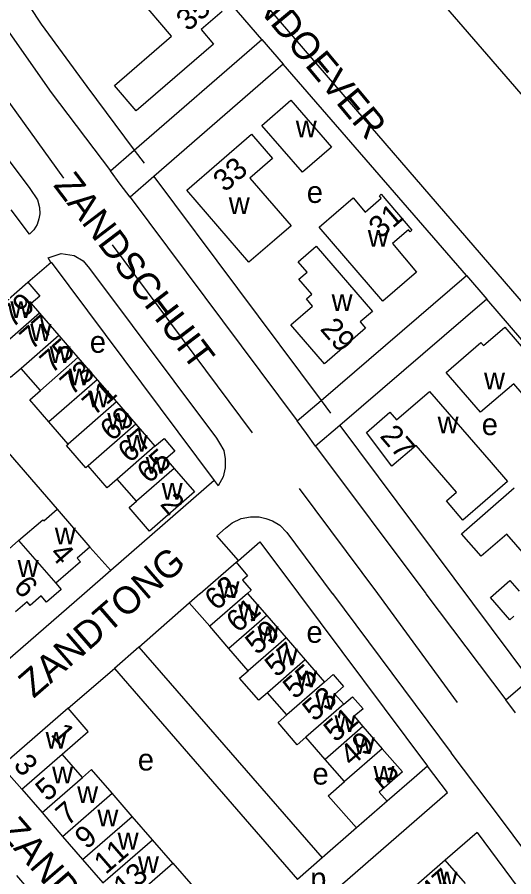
# Model space of a CAD drawing. Extents: x 155854 to 157362, y 383621 to 384685.
# Drawn here: x 156615.7 to 156707.1, y 384447.9 to 384605.9 of the extents above; entities that cross this region are included whole.
import ezdxf

# ---------------------------------------------------------------- set-up
doc = ezdxf.new("R2010")
doc.units = 0
for name, color, linetype in [('BLT_Basislijn', 7, 'Continuous'), ('BLT_Bebouwing', 7, 'Continuous'), ('BLT_Centroide', 7, 'Continuous'), ('BLT_Huisnummer', 7, 'Continuous'), ('BLT_Huisnummer_ tussenligend', 7, 'Continuous'), ('BLT_Huisnummer_reeks', 7, 'Continuous'), ('BLT_Onderverdeling_panden', 7, 'Continuous'), ('BLT_Straatnaam', 7, 'Continuous'), ('BLT_Vlakafsluiter', 7, 'Continuous')]:
    doc.layers.add(name, color=color, linetype=linetype)

msp = doc.modelspace()

# ---------------------------------------------------------------- linework, layer by layer
at = {"layer": 'BLT_Basislijn'}
for p, q in [((156738.35, 384519.08), (156620.78, 384655.36)), ((156660.68, 384601.84), (156664.6, 384597.3)), ((156632.85, 384577.67), (156637.24, 384581.48)), ((156637.24, 384581.48), (156639.05, 384579.08)), ((156640.85, 384576.67), (156636.46, 384572.86)), ((156636.46, 384572.86), (156634.65, 384575.26)), ((156633.18, 384564.07), (156658.93, 384529.55)), ((156617.64, 384557.2), (156621.94, 384560.91)), ((156698.32, 384558.42), (156702.06, 384554.11)), ((156676.7, 384539.93), (156676.7, 384539.94)), ((156667.23, 384531.71), (156671.59, 384535.45)), ((156671.59, 384535.45), (156673.31, 384533.17)), ((156609.87, 384530.7), (156623.06, 384515.49)), ((156675.02, 384530.89), (156670.57, 384527.07)), ((156670.57, 384527.07), (156668.9, 384529.39)), ((156651.95, 384520.75), (156632.95, 384504.22)), ((156651.95, 384520.75), (156652.68, 384519.76)), ((156629.09, 384508.54), (156632.95, 384504.22)), ((156656.38, 384506.09), (156660.35, 384509.5)), ((156660.35, 384509.5), (156667.45, 384500)), ((156655.99, 384505.77), (156656.38, 384506.09)), ((156632.95, 384504.22), (156628.09, 384500)), ((156628.07, 384499.98), (156591.85, 384468.53)), ((156628.09, 384500), (156628.07, 384499.98)), ((156667.45, 384500), (156667.46, 384499.98)), ((156667.46, 384499.98), (156691.17, 384468.24)), ((156638.1, 384490.13), (156647.36, 384498.28)), ((156638.1, 384490.13), (156633.62, 384486.24)), ((156638.1, 384490.13), (156671.77, 384451.38)), ((156625.08, 384478.9), (156633.62, 384486.24)), ((156633.62, 384486.24), (156667.24, 384447.45)), ((156705.61, 384480.46), (156709.91, 384484.17)), ((156678.11, 384456.92), (156671.77, 384451.38)), ((156700.29, 384456.04), (156694.41, 384450.96)), ((156700.29, 384456.04), (156731.11, 384414.78)), ((156671.77, 384451.38), (156667.24, 384447.45))]:
    msp.add_line(p, q, dxfattribs=at)
for points in [[(156640.63, 384670.01), (156709.96, 384590.03), (156761.05, 384531.07)], [(156660.68, 384601.84), (156620.18, 384648.79)], [(156602.64, 384633.55), (156611.21, 384618.58), (156613.55, 384614.63), (156620.14, 384604.65), (156628.52, 384593.18), (156637.24, 384581.48)], [(156598.66, 384627.58), (156608.28, 384611.57), (156621.98, 384592.1), (156632.85, 384577.67)], [(156593.76, 384619.32), (156609.39, 384596.86), (156624.21, 384576.36)], [(156584.74, 384610.72), (156588.67, 384613.62), (156618, 384574.45), (156619.46, 384572.38), (156619.82, 384570.92), (156619.84, 384569.78), (156619.71, 384568.89), (156619.36, 384567.83), (156618.76, 384566.86), (156617.99, 384566.04), (156614.62, 384570.53)], [(156637.24, 384581.48), (156660.68, 384601.84)], [(156664.6, 384597.3), (156640.85, 384576.67)], [(156698.32, 384558.42), (156664.6, 384597.3)], [(156640.85, 384576.67), (156671.59, 384535.45)], [(156636.46, 384572.86), (156667.23, 384531.71)], [(156621.88, 384560.86), (156621.41, 384561.72), (156623.76, 384562.5), (156626.21, 384562.11), (156627.82, 384561.16), (156629.03, 384559.75), (156652.39, 384528.52), (156652.94, 384527.66), (156653.7, 384526.26), (156653.93, 384524.73), (156653.93, 384523.09), (156653.61, 384521.44), (156652.68, 384519.76)], [(156621.94, 384560.91), (156651.95, 384520.75)], [(156671.59, 384535.45), (156698.32, 384558.42)], [(156702.06, 384554.11), (156675.02, 384530.89)], [(156739.97, 384510.11), (156702.06, 384554.11)], [(156675.02, 384530.89), (156709.91, 384484.17)], [(156670.57, 384527.07), (156690.84, 384500)], [(156682.02, 384500), (156667.6, 384519.3)], [(156656.38, 384506.09), (156652.44, 384510.61), (156654.01, 384512.01), (156655.27, 384512.99), (156656.87, 384513.78), (156658.62, 384514.06), (156660.19, 384514.06), (156661.43, 384513.81), (156662.65, 384513.34), (156664, 384512.55), (156665.28, 384511.21), (156673.66, 384500)], [(156673.66, 384500), (156673.67, 384499.98)], [(156673.67, 384499.98), (156695.52, 384470.73)], [(156682.04, 384499.98), (156682.02, 384500)], [(156696.72, 384479.99), (156682.04, 384499.98)], [(156690.84, 384500), (156690.85, 384499.98)], [(156690.89, 384499.93), (156705.61, 384480.46)], [(156726.96, 384411.19), (156730.91, 384406.67), (156732.14, 384407.62), (156733.47, 384408.89), (156734.43, 384410.44), (156734.94, 384411.69), (156735.4, 384413.39), (156735.49, 384414.94), (156735.24, 384416.83), (156734.81, 384418.13), (156704.77, 384458.46), (156695.52, 384470.73)], [(156648.22, 384422.86), (156694.85, 384463.4), (156691.17, 384468.24)], [(156691.17, 384468.24), (156688.74, 384466.13), (156683.73, 384461.82)]]:
    msp.add_lwpolyline(points, dxfattribs=at)
at = {"layer": 'BLT_Bebouwing'}
for p, q in [((156644.1, 384602.46), (156634.31, 384613.86)), ((156653.39, 384607), (156649.52, 384603.65)), ((156649.52, 384603.65), (156651.83, 384600.98)), ((156633.58, 384593.4), (156644.1, 384602.46)), ((156651.83, 384600.98), (156637.61, 384588.7)), ((156637.61, 384588.7), (156633.58, 384593.4)), ((156660.73, 384586.05), (156666.06, 384590.66)), ((156666.06, 384590.66), (156673.49, 384582.05)), ((156668.16, 384577.45), (156660.73, 384586.05)), ((156646.91, 384574.14), (156658.83, 384584.41)), ((156658.83, 384584.41), (156662.67, 384579.95)), ((156673.49, 384582.05), (156668.16, 384577.45)), ((156662.67, 384579.95), (156658.49, 384576.36)), ((156658.32, 384560.9), (156646.91, 384574.14)), ((156663.01, 384564.94), (156658.32, 384560.9)), ((156609.12, 384549.79), (156617.64, 384557.2)), ((156619.81, 384551.5), (156623.34, 384547.43)), ((156623.34, 384547.43), (156626.88, 384543.36)), ((156626.88, 384543.36), (156630.43, 384539.27)), ((156630.43, 384539.27), (156633.97, 384535.2)), ((156685.45, 384531.91), (156691.56, 384537.15)), ((156691.56, 384537.15), (156702.88, 384524.08)), ((156633.97, 384535.2), (156637.51, 384531.12)), ((156679.94, 384529.62), (156684.25, 384533.32)), ((156684.25, 384533.32), (156685.45, 384531.91)), ((156625.09, 384527.44), (156621.54, 384531.54)), ((156637.51, 384531.12), (156641.04, 384527.06)), ((156684.63, 384523.39), (156679.94, 384529.62)), ((156689.09, 384527.22), (156684.63, 384523.39)), ((156696.49, 384518.6), (156689.09, 384527.22)), ((156702.88, 384524.08), (156705.89, 384520.57)), ((156644.57, 384522.99), (156648.3, 384518.69)), ((156697.44, 384510.99), (156707.13, 384519.39)), ((156705.89, 384520.57), (156697.66, 384513.5)), ((156648.3, 384518.69), (156640.01, 384511.48)), ((156694.64, 384517.02), (156696.49, 384518.6)), ((156697.66, 384513.5), (156694.64, 384517.02)), ((156623.06, 384515.49), (156629.09, 384508.54)), ((156701.04, 384506.84), (156697.44, 384510.99)), ((156705.75, 384510.91), (156701.04, 384506.84)), ((156711.92, 384503.78), (156705.75, 384510.91)), ((156649.34, 384500), (156655.99, 384505.77)), ((156702.75, 384499.28), (156706.34, 384502.39)), ((156706.34, 384502.39), (156708.04, 384500.42)), ((156647.36, 384498.28), (156649.32, 384499.98)), ((156649.32, 384499.98), (156649.34, 384500)), ((156706.31, 384495.18), (156702.75, 384499.28)), ((156617.51, 384498.48), (156615.4, 384496.65)), ((156618.11, 384497.8), (156617.51, 384498.48)), ((156707.06, 384495.81), (156706.31, 384495.18)), ((156627.71, 384466.19), (156623.98, 384470.48)), ((156683.73, 384461.82), (156678.11, 384456.92)), ((156644.32, 384450.43), (156648.06, 384446.12)), ((156694.41, 384450.96), (156685.32, 384443.08)), ((156698.15, 384446.66), (156694.41, 384450.96)), ((156619.35, 384443.86), (156615.62, 384448.16))]:
    msp.add_line(p, q, dxfattribs=at)
for points in [[(156658.49, 384576.36), (156666.07, 384567.58), (156663.01, 384564.94)], [(156617.64, 384557.2), (156619.85, 384554.66), (156618.26, 384553.28), (156619.81, 384551.5)], [(156701.47, 384545.58), (156705.38, 384548.95), (156719.42, 384532.65), (156712.37, 384526.58), (156708.8, 384530.72), (156711.68, 384533.21), (156707.05, 384538.55)], [(156694.59, 384540.65), (156700.96, 384546.14), (156701.47, 384545.58)], [(156616.42, 384541.38), (156614.46, 384539.68), (156610.93, 384543.75), (156612.89, 384545.45)], [(156619.96, 384537.31), (156616.42, 384541.38)], [(156707.05, 384538.55), (156700.93, 384533.3), (156694.59, 384540.65)], [(156621.54, 384531.54), (156618, 384535.61), (156619.96, 384537.31)], [(156628.75, 384523.47), (156628.32, 384523.11), (156624.78, 384527.19), (156625.09, 384527.44)], [(156641.04, 384527.06), (156642.72, 384528.49), (156644.72, 384526.18), (156643.05, 384524.73), (156644.57, 384522.99)], [(156634.12, 384521.01), (156632.27, 384519.41), (156628.75, 384523.47)], [(156637.63, 384516.96), (156634.12, 384521.01)], [(156640.01, 384511.48), (156636.28, 384515.79), (156637.63, 384516.96)], [(156615.96, 384509.72), (156620.39, 384513.56), (156620.59, 384513.34), (156623.06, 384515.49)], [(156609.37, 384503.59), (156611.48, 384505.43), (156611.28, 384505.65), (156615.96, 384509.72)], [(156629.09, 384508.54), (156626.75, 384506.51), (156627.35, 384505.83), (156622.79, 384501.87)], [(156655.99, 384505.77), (156658.08, 384503.24), (156657.15, 384502.44), (156658.76, 384500.59), (156658.07, 384500)], [(156622.79, 384501.87), (156623.77, 384500.74), (156621.1, 384498.41), (156620.12, 384499.54), (156618.11, 384497.8)], [(156658.07, 384500), (156658.09, 384499.98)], [(156658.09, 384499.98), (156661.61, 384495.93)], [(156658.09, 384499.98), (156658.09, 384499.98)], [(156651.11, 384493.97), (156647.36, 384498.28)], [(156661.61, 384495.93), (156665.15, 384491.86)], [(156654.65, 384489.89), (156651.11, 384493.97)], [(156665.15, 384491.86), (156668.68, 384487.79)], [(156658.19, 384485.81), (156654.65, 384489.89)], [(156668.68, 384487.79), (156672.23, 384483.71)], [(156661.73, 384481.74), (156660.14, 384480.36), (156656.6, 384484.43), (156658.19, 384485.81)], [(156672.23, 384483.71), (156673.82, 384485.08), (156675.73, 384482.89), (156674.14, 384481.5), (156675.77, 384479.63)], [(156665.27, 384477.67), (156661.73, 384481.74)], [(156675.77, 384479.63), (156677.39, 384481.03), (156679.32, 384478.78), (156677.67, 384477.44), (156679.31, 384475.55)], [(156625.08, 384478.9), (156612.84, 384468.27)], [(156623.98, 384470.48), (156628.77, 384474.64), (156625.08, 384478.9)], [(156668.82, 384473.59), (156667.22, 384472.2), (156663.68, 384476.28), (156665.27, 384477.67)], [(156679.31, 384475.55), (156682.86, 384471.47)], [(156672.36, 384469.51), (156668.82, 384473.59)], [(156682.86, 384471.47), (156686.57, 384467.2)], [(156675.9, 384465.43), (156672.36, 384469.51)], [(156612.84, 384468.27), (156616.54, 384464.01)], [(156633.16, 384463.28), (156629.37, 384467.64), (156627.71, 384466.19)], [(156686.57, 384467.2), (156682.29, 384463.48), (156683.73, 384461.82)], [(156616.54, 384464.01), (156620.27, 384459.72)], [(156678.11, 384456.92), (156672.93, 384462.83), (156675.9, 384465.43)], [(156636.85, 384459.03), (156633.16, 384463.28)], [(156620.27, 384459.72), (156624.06, 384455.36)], [(156640.59, 384454.73), (156636.85, 384459.03)], [(156624.06, 384455.36), (156627.74, 384451.12)], [(156644.32, 384450.43), (156640.59, 384454.73)], [(156627.74, 384451.12), (156631.48, 384446.82)]]:
    msp.add_lwpolyline(points, dxfattribs=at)
for points in [[(156671.23, 384567.32), (156677.48, 384572.71), (156679.72, 384570.11), (156682.67, 384572.66), (156682.32, 384573.07), (156682.67, 384573.38), (156688.32, 384566.81), (156687.97, 384566.5), (156687.66, 384566.86), (156684.72, 384564.34), (156689.16, 384559.08), (156682.96, 384553.74)], [(156666.04, 384549.36), (156670.04, 384552.81), (156668.89, 384554.15), (156669.89, 384555.01), (156667.52, 384557.76), (156669.02, 384559.05), (156667.37, 384560.97), (156670.69, 384563.83), (156681.03, 384551.85), (156678.78, 384549.91), (156679.79, 384548.74), (156672.22, 384542.21)]]:
    msp.add_lwpolyline(points, close=True, dxfattribs=at)
at = {"layer": 'BLT_Onderverdeling_panden'}
for p, q in [((156619.81, 384551.5), (156612.89, 384545.45)), ((156623.34, 384547.43), (156616.42, 384541.38)), ((156626.88, 384543.36), (156619.96, 384537.31)), ((156630.43, 384539.27), (156621.54, 384531.54)), ((156633.97, 384535.2), (156625.09, 384527.44)), ((156637.51, 384531.12), (156628.75, 384523.47)), ((156641.04, 384527.06), (156634.12, 384521.01)), ((156644.57, 384522.99), (156637.63, 384516.96)), ((156615.96, 384509.72), (156622.79, 384501.87)), ((156658.09, 384499.98), (156651.11, 384493.97)), ((156658.09, 384499.98), (156658.09, 384499.98)), ((156661.61, 384495.93), (156654.65, 384489.89)), ((156665.15, 384491.86), (156658.19, 384485.81)), ((156668.68, 384487.79), (156661.73, 384481.74)), ((156672.23, 384483.71), (156665.27, 384477.67)), ((156675.77, 384479.63), (156668.82, 384473.59)), ((156679.31, 384475.55), (156672.36, 384469.51)), ((156682.86, 384471.47), (156675.9, 384465.43)), ((156620.27, 384459.72), (156627.71, 384466.19)), ((156627.74, 384451.12), (156636.85, 384459.03)), ((156631.48, 384446.82), (156640.59, 384454.73)), ((156635.22, 384442.52), (156644.32, 384450.43))]:
    msp.add_line(p, q, dxfattribs=at)
for points in [[(156616.54, 384464.01), (156623.98, 384470.48)], [(156624.06, 384455.36), (156633.16, 384463.28)]]:
    msp.add_lwpolyline(points, dxfattribs=at)
at = {"layer": 'BLT_Vlakafsluiter'}
for p, q in [((156634.65, 384575.26), (156632.85, 384577.67)), ((156668.9, 384529.39), (156667.23, 384531.71)), ((156707.36, 384478.07), (156705.61, 384480.46))]:
    msp.add_line(p, q, dxfattribs=at)

# ---------------------------------------------------------------- texts
at = {"layer": 'BLT_Centroide'}
for s, p in [('w', (156666.94, 384583.84)), ('e', (156668.97, 384571.79)), ('w', (156654.62, 384569.73)), ('w', (156680.19, 384563.73)), ('w', (156673.53, 384551.94)), ('w', (156614.45, 384550.62)), ('w', (156618.12, 384546.44)), ('e', (156629.06, 384544.25)), ('w', (156621.65, 384542.38)), ('w', (156625.19, 384538.28)), ('w', (156701.57, 384537.53)), ('w', (156628.74, 384534.22)), ('w', (156632.27, 384530.12)), ('w', (156693.03, 384529.44)), ('e', (156701.15, 384529.11)), ('w', (156635.81, 384526.06)), ('w', (156639.35, 384522)), ('w', (156642.28, 384517.25)), ('w', (156622.62, 384509.03)), ('w', (156615.78, 384503.06)), ('w', (156652.72, 384499.16)), ('w', (156656.35, 384494.94)), ('e', (156668.91, 384490.93)), ('w', (156659.9, 384490.88)), ('w', (156663.44, 384486.81)), ('w', (156666.98, 384482.72)), ('w', (156670.52, 384478.66)), ('w', (156674.06, 384474.56)), ('w', (156620.93, 384471.47)), ('w', (156677.61, 384470.5)), ('e', (156637.89, 384467.46)), ('w', (156622.12, 384465.09)), ('e', (156670.02, 384464.87)), ('w', (156681.23, 384465.2)), ('w', (156626.73, 384461.5)), ('w', (156630.45, 384457.19)), ('w', (156634.17, 384452.94)), ('w', (156637.91, 384448.62)), ('p', (156669.61, 384445.62)), ('w', (156692.81, 384445.81))]:
    msp.add_text(s, height=4, dxfattribs=at).set_placement(p)
at = {"layer": 'BLT_Huisnummer'}
for s, rotation, p in [('35', 41.0839, (156647.12, 384603.17)), ('33', 40.9787, (156653.91, 384573.63)), ('31', 40.7387, (156682.52, 384565.08)), ('79', 41.155, (156614.79, 384548.68)), ('29', 310.7849, (156671.27, 384548.55)), ('75', 41.155, (156622.05, 384540.3)), ('71', 41.155, (156629.84, 384532.55)), ('27', 310.7849, (156682.27, 384528.87)), ('65', 41.155, (156639.9, 384520.05)), ('2', 311.1603, (156641.84, 384516.34)), ('4', 310.985, (156621.5, 384507.21)), ('63', 40.9905, (156652.34, 384496.7)), ('59', 40.9905, (156659.82, 384488.57)), ('55', 40.9905, (156666.76, 384480.42)), ('51', 40.9905, (156674.25, 384472.51)), ('2', 309.7299, (156681.26, 384466.12)), ('7', 40.9786, (156624.96, 384457.14)), ('11', 40.9786, (156631.98, 384448.23)), ('47', 41.1425, (156691.98, 384442.89))]:
    msp.add_text(s, height=4, rotation=rotation, dxfattribs=at).set_placement(p)
at = {"layer": 'BLT_Huisnummer_ tussenligend'}
for s, rotation, p in [('77', 41.155, (156618.34, 384544.65)), ('73', 41.155, (156625.74, 384536.28)), ('69', 41.155, (156633.12, 384527.82)), ('67', 41.155, (156636.38, 384523.84)), ('6', 310.985, (156614.83, 384501.11)), ('61', 40.9905, (156656.31, 384492.62)), ('57', 40.9905, (156663.42, 384484.45)), ('53', 40.9905, (156670.34, 384476.32)), ('49', 40.9905, (156677.21, 384468.05)), ('5', 40.9786, (156621.23, 384461.62)), ('9', 40.9786, (156628.47, 384452.83)), ('13', 40.9786, (156635.55, 384443.95))]:
    msp.add_text(s, height=4, rotation=rotation, dxfattribs=at).set_placement(p)
at = {"layer": 'BLT_Huisnummer_reeks'}
for s, rotation, p in [('1', 310.9443, (156621.71, 384474.05)), ('3', 310.9917, (156614.85, 384468.35))]:
    msp.add_text(s, height=4, rotation=rotation, dxfattribs=at).set_placement(p)
at = {"layer": 'BLT_Straatnaam'}
for s, rotation, p in [('ZANDOEVER', 309.7609, (156653.52, 384615.08)), ('ZANDSCHUIT', 307.2809, (156622.23, 384575)), ('ZANDTONG', 40.9818, (156618.71, 384480.61)), ('ZANDTONG', 310.9823, (156612.18, 384456.2))]:
    msp.add_text(s, height=5, rotation=rotation, dxfattribs=at).set_placement(p)

doc.saveas('drawing.dxf')
